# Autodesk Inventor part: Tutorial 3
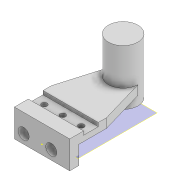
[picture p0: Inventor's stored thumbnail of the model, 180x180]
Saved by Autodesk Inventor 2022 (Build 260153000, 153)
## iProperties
Created: 2021-03
Part Number: Tutorial 3
Material: Generic
Document SubType Name: Modeling
Designer: ASUS Laptop
Density: 1 g/cm^3
Appearance: Default
Author: ASUS Laptop
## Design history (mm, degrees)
sketch "Sketch1"
  geometry: L1 (0, 0)-(30, 0); L2 (30, 0)-(30, -15); L3 (30, -15)-(26, -15); L4 (26, -15)-(26, -31); L5 (26, -31)-(30, -31); L6 (30, -31)-(30, -40); L7 (20, -40)-(20, -10); L8 (20, -10)-(0, -10); L9 (0, -10)-(0, 0); L10 (20, -40)-(30, -40)
  constraints: 20 end point, 8 perpendicular, 1 horizontal, 1 parallel, 1 point on line
  dimensions: "d0" = 16 distance of L3.end L4.end; "d1" = 15 distance of L1.end L2.end; "d2" = 40 distance between parallel lines of L1 L10; "d3" = 30 distance between parallel lines of L9 L2; "d4" = 4 distance between parallel lines of L4 L2; "d5" = 10 distance between parallel lines of L8 L1
extrude "Extrusion1" new body sketch "Sketch1" stored distance "d6" = 60; taper "d7" = 0 deg
sketch "Sketch4"
  geometry: L1 (0, 9)-(60, 9) reference; L2 (0, 9)-(14, 57); L3 (14, 57)-(46, 57); L4 (46, 57)-(60, 9); L5 (60, 9)-(0, 9); L6 (30, -31)-(30, 84.04)
  constraints: 10 end point, 1 collinear, 1 parallel, 1 vertical, 1 other
  dimensions: "d8" = 32 distance of L2.end L3.end; "d9" = 48 distance between parallel lines of L3 L1
extrude "Extrusion2" join sketch "Sketch4" distance "d10" = 10; taper "d11" = 0 deg
workplane "Work Plane1"
sketch "Sketch5"
  geometry: L1 (14, -78)-(46, -78) reference; L2 (0, 0)-(0, 10) reference; C1 r 16 at (30, -78); 1 further point
  constraints: 1 centre point, 1 midpoint
  dimensions: "d13" = 32 diameter of C1; "d14" = 30 distance from line of L2 C1.centre
extrude "Extrusion3" join sketch "Sketch5" distance "d15" = 60; taper "d16" = 0 deg
sketch "Sketch6"
  geometry: L1 (-6.213, 7.5)-(70.808, 7.5); L2 (0, -15)-(60, -15) reference; L3 (0, 0)-(0, 16) reference; C1 r 3 at (10, 7.5); C2 r 3 at (30, 7.5); C3 r 3 at (50, 7.5); 1 further point
  constraints: 3 centre point, 3 point on line, 2 end point, 2 equal radius, 1 horizontal
  dimensions: "d17" = 22.5 distance between parallel lines of L2 L1; "d18" = 10 distance from line of C1.centre L3; "d19" = 20 distance of C2.centre C1.centre; "d20" = 20 distance of C3.centre C2.centre; "d21" = 6 diameter of C1
extrude "Extrusion4" cut sketch "Sketch6" distance "d22" = 60; taper "d23" = 0 deg
sketch "Sketch7"
  geometry: 1 further point
sketch "Sketch8"
  geometry: L1 (10, 10)-(52.331, 10); L2 (0, 0)-(60, 0) reference; L3 (0, 0)-(0, 30) reference; C1 r 6 at (10, 10); C2 r 6 at (40, 10); 1 further point
  constraints: 2 centre point, 2 end point, 1 equal radius, 1 horizontal, 1 point on line
  dimensions: "d24" = 10 distance between parallel lines of L2 L1; "d25" = 10 distance from line of L3 L1.start; "d26" = 30 distance of C2.centre L1.start; "d27" = 12 diameter of C2
extrude "Extrusion5" cut sketch "Sketch8" stored distance "d28" = 10; taper "d29" = 0 deg
body "Solid1"
